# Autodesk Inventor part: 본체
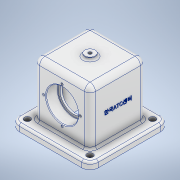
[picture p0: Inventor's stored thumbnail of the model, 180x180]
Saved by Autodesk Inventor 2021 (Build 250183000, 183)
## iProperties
Created: 2022-07
Part Number: 본체
Material: 알루미늄 6061
Document SubType Name: Modeling
Designer: i
Mass: 1058.33 g
Surface Area: 726.505 cm^2
Volume: 391.974 cm^3
Density: 2.7 g/cm^3
Appearance: 알루미늄 - 평지
Author: i
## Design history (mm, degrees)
sketch "스케치1"
  geometry: 1 further point
sketch "스케치2"
  geometry: L1 (58, -58)-(-58, -58); L2 (-58, -58)-(-58, 58); L3 (-58, 58)-(58, 58); L4 (58, 58)-(58, -58); L5 (58, -58)-(-58, 58); L6 (-58, -58)-(58, 58); 1 further point
  constraints: 12 end point, 2 midpoint, 2 parallel, 1 horizontal, 1 perpendicular
  dimensions: "d0" = 116 distance of L1.start L1.end; "d1" = 116 distance of L1.end L2.end
extrude "돌출1" new body sketch "스케치2" distance "d2" = 10; taper "d3" = 0 deg
sketch "스케치3"
  geometry: L1 (-41, 41)-(41, 41); L2 (41, 41)-(41, -41); L3 (41, -41)-(-41, -41); L4 (-41, -41)-(-41, 41); L5 (-41, 41)-(41, -41); L6 (41, 41)-(-41, -41); 1 further point
  constraints: 12 end point, 2 midpoint, 2 parallel, 1 horizontal, 1 perpendicular
  dimensions: "d4" = 82 distance of L1.start L1.end; "d5" = 82 distance of L1.end L2.end
extrude "돌출2" join sketch "스케치3" distance "d6" = 80; taper "d7" = 0 deg
node "작업 평면1"
sketch "스케치5"
  geometry: C1 r 7.5 at (0, 0); 1 further point
  constraints: 1 centre point, 1 coincident
  dimensions: "d9" = 15 diameter of C1
extrude "돌출3" join sketch "스케치5" stored distance "d10" = 80; taper "d11" = 0 deg
sketch "스케치7"
  geometry: L1 (-17, -10)-(99, -10) reference; C1 r 23.5 at (41, 38); 2 further points
  constraints: 1 centre point, 1 midpoint, 1 vertical alignment
  dimensions: "d12" = 47 diameter of C1; "d13" = 48 distance from line of L1 C1.centre
extrude "돌출4" cut sketch "스케치7" distance "d14" = 17; taper "d15" = 0 deg
sketch "스케치8"
  geometry: C1 r 23.5 at (0, 0) reference; C2 r 20 at (0, 0); 1 further point
  constraints: 1 centre point, 1 coincident
  dimensions: "d16" = 40 diameter of C2
extrude "돌출5" cut sketch "스케치8" stored distance "d17" = 0; taper "d18" = 0 deg
sketch "스케치9"
  geometry: C1 r 20 at (41, 38) reference; C2 r 20 at (41, 38) reference; C3 r 23.5 at (41, 38); 1 further point
  constraints: 1 centre point, 1 coincident
  dimensions: "d19" = 47 diameter of C3
extrude "돌출6" cut sketch "스케치9" distance "d20" = 17; taper "d21" = 0 deg
sketch "스케치10" dims "d22" = 54
  geometry: L1 (41, 38)-(41, 65); C1 r 23.5 at (41, 38) reference; 2 further points
  constraints: 2 coincident, 2 end point, 1 vertical, 1 vertical alignment, 2 other
hole "구멍1" sketch "스케치10" at (41, 65) diameter "d23" = 3.242; stored, may be unused: countersink angle "d27" = 90 deg, drill point angle "d29" = 118 deg; dims "d24" = 8, "d25" = 4, "d26" = 2, "d28" = 10
sketch "스케치11"
  geometry: C1 r 7.5 at (0, 0) reference; 2 further points
  constraints: 1 coincident
hole "구멍2" sketch "스케치11" at (0, 0) diameter "d33" = 4.917; stored, may be unused: countersink angle "d37" = 90 deg, drill point angle "d39" = 0 deg; dims "d34" = 10, "d35" = 4, "d36" = 2, "d38" = 10
fillet "모깎기1" dims "d40" = 8
fillet "모깎기2" dims "d41" = 12
sketch "스케치13"
  geometry: A1 r 12 centre (-46, 46) between (-46, 58) and (-58, 46) reference; A2 r 12 centre (46, 46) between (58, 46) and (46, 58) reference; A3 r 12 centre (46, -46) between (46, -58) and (58, -46) reference; A4 r 12 centre (-46, -46) between (-58, -46) and (-46, -58) reference; 5 further points
  constraints: 4 coincident
hole "구멍3" sketch "스케치13" at (-46, 46), (46, 46), (46, -46), (-46, -46) diameter "d42" = 9; stored, may be unused: countersink angle "d46" = 90 deg, drill point angle "d48" = 0 deg; dims "d43" = 12, "d44" = 4, "d45" = 2, "d47" = 30
chamfer "모따기1" distance "d49" = 1; stored, may be unused: second distance "d50" = 2, angle "d51" = 45 deg
fillet "모깎기3" dims "d52" = 3
sketch "스케치14"
  geometry: L1 (90, 33)-(90, -33) reference; L2 (0, -46)-(0, 46) reference; A1 r 8 centre (82, 33) between (90, 33) and (82, 41) reference; A2 r 8 centre (82, -33) between (82, -41) and (90, -33) reference; 1 further point
sketch "스케치15"
  geometry: L1 (30, 21)-(-30, 21); L2 (-30, 21)-(-30, -21); L3 (-30, -21)-(30, -21); L4 (30, -21)-(30, 21); L5 (30, 21)-(-30, -21); L6 (-30, 21)-(30, -21); L7 (-33, -33)-(33, -33) reference; 2 further points
  constraints: 12 end point, 2 midpoint, 2 parallel, 1 horizontal, 1 perpendicular
  dimensions: "d53" = 42 distance of L3.end L1.start; "d55" = 60 distance of L2.end L3.end
extrude "돌출7" cut sketch "스케치15" distance "d56" = 80; taper "d57" = 0 deg
fillet "모깎기4" dims "d58" = 3
sketch "스케치16"
  geometry: L1 (-13, -82)-(79, -82) reference; 3 further points
  constraints: 1 midpoint, 1 vertical alignment, 1 other
  dimensions: "d59" = 48 distance from line of L1 point (33, -34)
feature "엠보싱1" sketch "스케치16" dims "d0" = 116, "d1" = 116, "d60" = 0.5, "d61" = 0
fillet "모깎기5" dims "d62" = 0.6
fillet "모깎기6" dims "d63" = 0.6
fillet "모깎기7" dims "d64" = 3
node "솔리드1"
pattern_circular "원형 패턴1" dims angle "d31" = 360 deg
mirror "미러1"
feature "A9D066F2-1C7D-4E18-AEED-F7BC21143FA4" dims "d33" = 4.917, "d34" = 10, "d35" = 4, "d36" = 2, "d37" = 90 deg, "d38" = 10, "d39" = 0
other parameters: "d8" = 4
